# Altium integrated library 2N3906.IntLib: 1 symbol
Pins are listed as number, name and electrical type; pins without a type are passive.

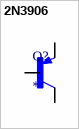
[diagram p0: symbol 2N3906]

## 2N3906
designator Q?
BJT, TO-92, 40V, 200mA, PNP, 0.625W, 150Â°C; MF: Diotec Semiconductor; MP: 2N3906
footprint TO92254P460H750-3
pins: 1 E, 2 B, 3 C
